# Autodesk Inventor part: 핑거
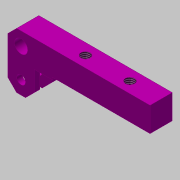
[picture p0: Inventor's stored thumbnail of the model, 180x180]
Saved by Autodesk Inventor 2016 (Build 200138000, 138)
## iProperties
Created: 2020-02
Part Number: 핑거
Material: 알루미늄 6061
Document SubType Name: Modeling
Designer: mduedu
Density: 1 g/cm^3
Appearance: 자홍색
Author: mduedu
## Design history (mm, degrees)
sketch "스케치1"
  geometry: L1 (0, 0)-(12, 0); L2 (64, 14)-(64, 25); L3 (64, 25)-(0, 25); L4 (0, 25)-(0, 0); L5 (12, 0)-(12, 13); L6 (12, 13)-(20, 13); L7 (64, 14)-(20, 14); L8 (20, 14)-(20, 13)
  constraints: 16 end point, 2 horizontal, 2 parallel, 1 perpendicular, 1 vertical
  dimensions: "d0" = 64 distance of L2.end L3.end; "d2" = 12 distance of L1.start L1.end; "d3" = 25 distance of L3.end L1.start; "d4" = 11 distance of L2.start L2.end; "d5" = 12 distance between parallel lines of L6 L3; "d6" = 44 distance of L2.start L7.end
extrude "돌출1" new body sketch "스케치1" stored distance "d7" = 10; taper "d8" = 0 deg
chamfer "모따기1" distance "d9" = 4; stored, may be unused: second distance "d10" = 2, angle "d11" = 45 deg
sketch "스케치2"
  geometry: L1 (2.5, -4)-(7.5, -4); L2 (7.5, -4)-(7.5, 9); L3 (7.5, 9)-(2.5, 9); L4 (2.5, 9)-(2.5, -4); L5 (10, 21)-(0, 21) reference; 2 further points
  constraints: 8 end point, 2 parallel, 1 coincident, 1 horizontal, 1 midpoint, 1 perpendicular
  dimensions: "d12" = 5 distance of L1.start L1.end; "d15" = 12 distance between parallel lines of L3 L5
extrude "돌출2" cut sketch "스케치2" stored distance "d16" = 10; taper "d17" = 0 deg
sketch "스케치3"
  geometry: L1 (0, 4)-(0, 21) reference; L2 (4, 25)-(64, 25) reference; C1 r 2 at (6, 6); C2 r 3 at (6, 19); 1 further point
  constraints: 2 centre point, 1 vertical alignment
  dimensions: "d18" = 6 distance from line of C2.centre L1; "d19" = 6 distance from line of C2.centre L2; "d20" = 13 distance of C1.centre C2.centre; "d21" = 6 diameter of C2; "d22" = 4 diameter of C1
extrude "돌출3" cut sketch "스케치3" stored distance "d23" = 10; taper "d24" = 0 deg
sketch "스케치4"
  geometry: L1 (0, 10)-(0, 0) reference; 3 further points
  constraints: 2 horizontal alignment
  dimensions: "d25" = 14 distance from line of point (-14, 5) L1; "d26" = 20 distance of point (-34, 5) point (-14, 5)
hole "구멍1" sketch "스케치4" at (-34, 5), (-14, 5) diameter "d27" = 4.134; stored, may be unused: countersink angle "d31" = 90 deg, drill point angle "d33" = 118 deg; dims "d28" = 6, "d29" = 4, "d30" = 2, "d32" = 8
node "솔리드1"
